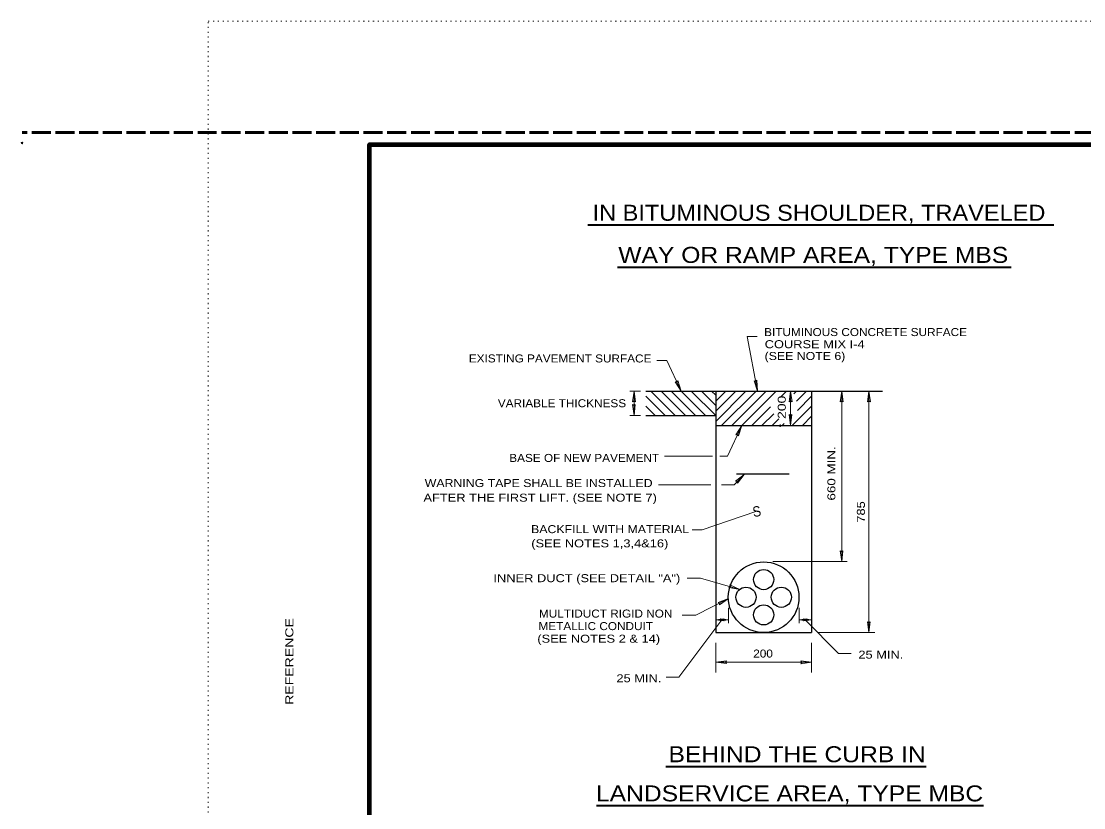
# Model space of a CAD drawing. Extents: x 312583 to 312854, y 144419 to 144597.
# Drawn here: x 312583.5 to 312684.3, y 144522.1 to 144596.8 of the extents above; entities that cross this region are included whole.
import ezdxf
from ezdxf.enums import TextEntityAlignment as Align

# ---------------------------------------------------------------- set-up
doc = ezdxf.new("R2010")
doc.units = 0
doc.header["$LTSCALE"] = 0.3
doc.header["$PDMODE"] = 32
doc.header["$PDSIZE"] = 0.15
doc.linetypes.add('DOTTED', pattern=[1.5, 0.3, -1.2])
doc.linetypes.add('LONG_DASHED', pattern=[7.5, 6, -1.5])
for name, color, linetype, lineweight in [('1', 7, 'Continuous', 13), ('62', 7, 'DOTTED', 13), ('63', 7, 'LONG_DASHED', 60)]:
    doc.layers.add(name, color=color, linetype=linetype, lineweight=lineweight)

msp = doc.modelspace()

# ---------------------------------------------------------------- linework, layer by layer
at = {"layer": '1', "lineweight": 40}
for p, q in [((312637.2329, 144577.433), (312681.4769, 144577.433)), ((312640.0354, 144573.431), (312677.4133, 144573.431)), ((312644.6341, 144526.0033), (312669.3379, 144526.0033)), ((312638.0568, 144522.282), (312674.7966, 144522.282))]:
    msp.add_line(p, q, dxfattribs=at)
at = {"layer": '1'}
for p, q in [((312644.7475, 144564.5607), (312643.7891, 144564.5607)), ((312644.7475, 144564.5607), (312646.0968, 144561.655)), ((312642.2328, 144561.655), (312641.2131, 144561.655)), ((312641.6195, 144561.655), (312641.6195, 144559.3397)), ((312645.5371, 144559.3397), (312643.2218, 144561.655)), ((312646.4955, 144559.3397), (312644.1801, 144561.655)), ((312647.4538, 144559.3397), (312645.1385, 144561.655)), ((312648.4121, 144559.3397), (312646.0968, 144561.655)), ((312649.3705, 144559.3397), (312647.0551, 144561.655)), ((312649.3705, 144560.298), (312648.0135, 144561.655)), ((312649.3705, 144561.2564), (312648.9718, 144561.655)), ((312649.3705, 144558.78), (312652.2455, 144561.655)), ((312649.3705, 144559.7384), (312651.2871, 144561.655)), ((312649.3705, 144560.6967), (312650.3288, 144561.655)), ((312649.9301, 144558.3814), (312653.2038, 144561.655)), ((312650.8885, 144558.3814), (312654.1621, 144561.655)), ((312651.8468, 144558.3814), (312655.1205, 144561.655)), ((312655.5115, 144561.0877), (312656.0788, 144561.655)), ((312656.4851, 144561.655), (312656.4851, 144558.3814)), ((312656.7918, 144561.4097), (312657.0371, 144561.655)), ((312657.0448, 144560.7044), (312657.9955, 144561.655)), ((312661.3305, 144561.655), (312661.3305, 144545.4554)), ((312663.9141, 144561.655), (312663.9141, 144538.7164)), ((312644.5788, 144559.3397), (312642.7388, 144561.1797)), ((312657.1215, 144559.8227), (312658.4785, 144561.1797)), ((312643.6205, 144559.3397), (312642.7388, 144560.2214)), ((312652.8051, 144558.3814), (312654.5685, 144560.1524)), ((312656.6385, 144558.3814), (312658.4785, 144560.2214)), ((312642.2328, 144559.3397), (312641.2131, 144559.3397)), ((312653.7635, 144558.3814), (312654.8751, 144559.493)), ((312654.7218, 144558.3814), (312655.3581, 144559.0177)), ((312657.5968, 144558.3814), (312658.4785, 144559.263)), ((312650.4975, 144555.4757), (312651.8468, 144558.3814)), ((312655.6801, 144558.3814), (312655.8871, 144558.5884)), ((312649.0561, 144555.4757), (312644.5251, 144555.4757)), ((312650.4975, 144555.4757), (312649.7538, 144555.4757)), ((312651.1108, 144552.754), (312652.1381, 144553.789)), ((312648.9181, 144552.754), (312643.9271, 144552.754)), ((312651.1108, 144552.754), (312649.9301, 144552.754)), ((312648.0901, 144548.4914), (312653.1885, 144550.2164)), ((312648.0901, 144548.4914), (312647.1318, 144548.4914)), ((312654.8061, 144545.4554), (312661.8595, 144545.4554)), ((312647.9291, 144543.8837), (312646.6718, 144543.8837)), ((312651.6551, 144542.8027), (312647.9291, 144543.8837)), ((312647.4845, 144540.3724), (312650.5818, 144541.944)), ((312650.5895, 144541.0624), (312650.5895, 144539.6057)), ((312657.2825, 144541.0624), (312657.2825, 144539.6057)), ((312649.9685, 144539.9277), (312645.8821, 144534.469)), ((312647.4845, 144540.3724), (312646.1811, 144540.3724)), ((312649.3781, 144539.92), (312650.5818, 144539.92)), ((312657.2825, 144539.9277), (312658.4785, 144539.9277)), ((312659.0611, 144538.7164), (312664.4738, 144538.7164)), ((312649.3705, 144537.758), (312649.3705, 144534.9367)), ((312658.4785, 144537.758), (312658.4785, 144534.9367)), ((312658.4785, 144535.895), (312649.3705, 144535.895)), ((312644.6785, 144534.469), (312645.8821, 144534.469))]:
    msp.add_line(p, q, dxfattribs=at)
at = {"layer": '1', "lineweight": 25}
for p, q in [((312642.7388, 144561.655), (312665.1945, 144561.655)), ((312646.0968, 144561.655), (312660.9548, 144561.655)), ((312649.3705, 144561.655), (312649.3705, 144538.7164)), ((312658.4785, 144561.655), (312658.4785, 144538.7164)), ((312642.7388, 144559.3397), (312649.3705, 144559.3397)), ((312649.3705, 144558.3814), (312658.4785, 144558.3814)), ((312651.3561, 144553.789), (312656.3548, 144553.789)), ((312649.3705, 144538.7164), (312658.4785, 144538.7164))]:
    msp.add_line(p, q, dxfattribs=at)
at = {"layer": '1', "lineweight": 158}
msp.add_lwpolyline([(312616.5, 144423.1446), (312616.5, 144585.0846), (312849, 144585.0846)], dxfattribs=at)
at = {"layer": '1'}
for points in [[(312653.3035, 144566.853), (312652.3528, 144566.853), (312653.3495, 144561.655)], [(312657.8805, 144539.9277), (312661.0391, 144536.7307), (312662.2428, 144536.7307)]]:
    msp.add_lwpolyline(points, dxfattribs=at)
for points in [[(312645.7748, 144562.6517), (312646.0968, 144561.655), (312645.5371, 144562.5367), (312645.7058, 144562.4984)], [(312653.2805, 144562.6977), (312653.3495, 144561.655), (312653.0198, 144562.644), (312653.1731, 144562.575)], [(312641.4891, 144560.62), (312641.6195, 144561.655), (312641.7575, 144560.62), (312641.6195, 144560.7274)], [(312656.3548, 144560.62), (312656.4851, 144561.655), (312656.6231, 144560.62), (312656.4851, 144560.7274)], [(312661.2001, 144560.62), (312661.3305, 144561.655), (312661.4685, 144560.62), (312661.3305, 144560.7274)], [(312663.7838, 144560.62), (312663.9141, 144561.655), (312664.0521, 144560.62), (312663.9141, 144560.7274)], [(312641.7421, 144560.3747), (312641.6195, 144559.3397), (312641.4815, 144560.3747), (312641.6195, 144560.275)], [(312656.6078, 144559.4164), (312656.4851, 144558.3814), (312656.3471, 144559.4164), (312656.4851, 144559.3167)], [(312651.5248, 144557.3924), (312651.8468, 144558.3814), (312651.2871, 144557.5074), (312651.4558, 144557.538)], [(312651.4481, 144552.915), (312652.0845, 144553.7354), (312651.2565, 144553.1067), (312651.4251, 144553.076)], [(312661.4531, 144546.4904), (312661.3305, 144545.4554), (312661.1925, 144546.4904), (312661.3305, 144546.383)], [(312650.7045, 144543.2474), (312651.6551, 144542.8027), (312650.6278, 144542.9944), (312650.7658, 144543.0864)], [(312649.6005, 144541.5837), (312650.5818, 144541.944), (312649.7231, 144541.3537), (312649.7538, 144541.5147)], [(312650.1601, 144539.828), (312649.3781, 144539.92), (312650.1601, 144540.0274), (312650.0835, 144539.92)], [(312649.8075, 144540.0197), (312650.5818, 144539.92), (312649.8075, 144539.8204), (312649.8841, 144539.92)], [(312658.0568, 144539.8357), (312657.2825, 144539.9277), (312658.0568, 144540.035), (312657.9801, 144539.9277)], [(312657.7041, 144540.0197), (312658.4785, 144539.9277), (312657.7041, 144539.828), (312657.7808, 144539.9277)], [(312664.0368, 144539.7514), (312663.9141, 144538.7164), (312663.7761, 144539.7514), (312663.9141, 144539.6517)], [(312650.4055, 144535.7724), (312649.3705, 144535.895), (312650.4055, 144536.033), (312650.3058, 144535.895)], [(312657.4435, 144536.0254), (312658.4785, 144535.895), (312657.4435, 144535.757), (312657.5508, 144535.895)]]:
    msp.add_lwpolyline(points, close=True, dxfattribs=at)
at = {"layer": '1', "lineweight": 25}
for centre, radius in [((312653.9245, 144542.0744), 3.3542), ((312653.9238, 144543.7502), 0.9583), ((312652.2473, 144542.0737), 0.9583), ((312655.601, 144542.073), 0.9583), ((312653.9245, 144540.3965), 0.9583)]:
    msp.add_circle(centre, radius, dxfattribs=at)
at = {"layer": '1'}
for p in [(312583.526, 144585.2246), (312655.4808, 144558.366)]:
    msp.add_point(p, dxfattribs=at)
at = {"layer": '62'}
for p, q in [((312601.2, 144596.7846), (312853.5, 144596.7846)), ((312601.2, 144418.5846), (312601.2, 144596.7846))]:
    msp.add_line(p, q, dxfattribs=at)
at = {"layer": '63'}
msp.add_line((312851.75, 144586.2246), (312583.526, 144586.2246), dxfattribs=at)

# ---------------------------------------------------------------- texts
at = {"layer": '1'}
for s, width, p in [('IN BITUMINOUS SHOULDER, TRAVELED', 1.1, (312659.1762, 144577.8341)), ('WAY OR RAMP AREA, TYPE MBS', 1.15, (312658.6345, 144573.8321)), ('BEHIND THE CURB IN', 1.15, (312657.0997, 144526.4044)), ('LANDSERVICE AREA, TYPE MBC', 1.15, (312656.3845, 144522.6831))]:
    msp.add_text(s, height=1.52, dxfattribs=dict(at, width=width)).set_placement(p, align=Align.CENTER)
for s, width, p in [('BITUMINOUS CONCRETE SURFACE', 1.1, (312653.9698, 144566.8807)), ('COURSE MIX I-4', 1.2, (312654.0233, 144565.7288)), ('EXISTING PAVEMENT SURFACE', 1.1, (312625.938, 144564.3767)), ('(SEE NOTE 6)', 1.15, (312654.0141, 144564.6087)), ('VARIABLE THICKNESS', 1.1, (312628.6912, 144560.1217)), ('BASE OF NEW PAVEMENT', 1.1, (312629.7749, 144554.9267)), ('WARNING TAPE SHALL BE INSTALLED', 1.15, (312621.7521, 144552.5393)), ('AFTER THE FIRST LIFT. (SEE NOTE 7)', 1.2, (312621.631, 144551.1541)), ('BACKFILL WITH MATERIAL', 1.15, (312631.8449, 144548.1617)), ('(SEE NOTES 1,3,4&16)', 1.2, (312631.8635, 144546.8117)), ('INNER DUCT (SEE DETAIL "A")', 1.2, (312628.2736, 144543.5059)), ('MULTIDUCT RIGID NON', 1.1, (312632.5922, 144540.1425)), ('METALLIC CONDUIT', 1.1, (312632.5505, 144538.9536)), ('(SEE NOTES 2 & 14)', 1.2, (312632.4378, 144537.7578)), ('200', 1.1, (312652.9344, 144536.3449)), ('25 MIN.', 1.2, (312662.914, 144536.243)), ('25 MIN.', 1.2, (312639.9477, 144533.9966))]:
    msp.add_text(s, height=0.76, dxfattribs=dict(at, width=width)).set_placement(p)
for s, height, width, p in [('200 ', 0.76, 1.3, (312656.0226, 144559.0149)), ('660 MIN.', 0.76, 1.25, (312660.733, 144551.2587)), ('785 ', 0.76, 1.2, (312663.5346, 144549.1567)), ('REFERENCE                                                              ', 0.7682, 1.3, (312609.2854, 144531.8549))]:
    msp.add_text(s, height=height, rotation=90, dxfattribs=dict(at, width=width)).set_placement(p)
at = {"layer": '1', "width": 0.9}
msp.add_text('S', height=0.9804, rotation=10, dxfattribs=at).set_placement((312653.3536, 144549.7467), align=Align.CENTER)

doc.saveas('drawing.dxf')
